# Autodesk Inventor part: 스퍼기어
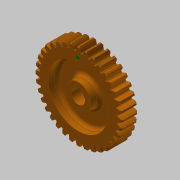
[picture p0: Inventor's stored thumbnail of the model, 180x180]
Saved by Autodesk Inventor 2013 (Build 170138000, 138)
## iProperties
Created: 2019-01
Part Number: 스퍼기어
Material: 알루미늄 6061
Document SubType Name: Modeling
Designer: mduedu
Density: 1 g/cm^3
Author: mduedu
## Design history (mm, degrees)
sketch "스케치1"
  geometry: C1 r 33.5 at (0, 0); C2 r 36 at (0, 0); C3 r 38 at (0, 0); 1 further point
  constraints: 3 centre point, 3 coincident
  dimensions: "d0" = 67 diameter of C1; "d2" = 72 diameter of C2; "d3" = 76 diameter of C3
extrude "돌출1" new body sketch "스케치1" distance "d4" = 14; taper "d5" = 0 deg
sketch "스케치2"
  geometry: L1 (0, 0)-(-38, 0); L2 (0, 0)-(0, 38); L3 (-0.57, 0)-(-0.57, 37.996); L4 (-1.57, 0)-(-1.57, 35.966); L5 (-2.07, 0)-(-2.07, 33.436); A1 r 38 centre (0, 0) between (-38, 0) and (0, 38) reference; A2 r 9.246 centre (7.162, 32.926) between (-0.57, 37.996) and (-2.07, 33.436); A3 r 9.246 centre (-7.162, 32.926) between (2.07, 33.436) and (0.57, 37.996); A4 r 33.5 centre (0, 0) between (2.07, 33.436) and (-2.07, 33.436); A5 r 38 centre (0, 0) between (0.57, 37.996) and (-0.57, 37.996); 2 further points
  constraints: 12 point on circle, 10 end point, 4 centre point, 3 parallel, 3 symmetric about line, 2 coincident, 1 horizontal, 1 perpendicular, 5 other
  dimensions: "d6" = 0.5 distance between parallel lines of L4 L5; "d8" = 1 distance between parallel lines of L3 L4; "d9" = 1.57 distance between parallel lines of L2 L4
extrude "돌출2" join sketch "스케치2" stored distance "d10" = 14; taper "d11" = 0 deg
chamfer "모따기1" distance "d12" = 1; stored, may be unused: second distance "d13" = 2, angle "d14" = 45 deg
fillet "모깎기1" dims "d15" = 0.5
sketch "스케치3"
  geometry: C1 r 11 at (0, 0); 1 further point
  constraints: 1 centre point, 1 coincident
  dimensions: "d19" = 22 diameter of C1
extrude "돌출3" join sketch "스케치3" distance "d20" = 7; taper "d21" = 0 deg
fillet "모깎기2" dims "d22" = 3
sketch "스케치4"
  geometry: C1 r 11 at (0, 0); C2 r 26 at (0, 0); 1 further point
  constraints: 2 centre point, 2 coincident
  dimensions: "d23" = 22 diameter of C1; "d24" = 52 diameter of C2
extrude "돌출4" cut sketch "스케치4" distance "d25" = 8; taper "d26" = 0 deg
fillet "모깎기3" dims "d27" = 3
sketch "스케치5" dims "d28" = 60
  geometry: C1 r 1.5 at (0, 30); 2 further points
  constraints: 2 vertical alignment, 1 centre point, 1 coincident, 2 other
  dimensions: "d29" = 3 diameter of C1
extrude "돌출5" join sketch "스케치5" distance "d30" = 0.5; taper "d31" = 0 deg
sketch "스케치6"
  geometry: L1 (-2, 5.657)-(2, 5.657); L2 (2, 5.657)-(2, 7.8); L3 (2, 7.8)-(-2, 7.8); L4 (-2, 7.8)-(-2, 5.657); A1 r 6 centre (0, 0) between (-2, 5.657) and (2, 5.657); 1 further point
  constraints: 8 end point, 2 parallel, 2 point on circle, 1 centre point, 1 coincident, 1 horizontal, 1 perpendicular
  dimensions: "d32" = 13.8 dimension on A1 L3; "d34" = 4 distance of L2.end L3.end; "d35" = 12 diameter of A1
extrude "돌출6" cut sketch "스케치6" stored distance "d36" = 0.5; taper "d37" = 0 deg
chamfer "모따기2" distance "d38" = 1; stored, may be unused: second distance "d39" = 2, angle "d40" = 45 deg
node "솔리드1"
pattern_circular "원형 패턴1" dims "d17" = 360 deg
